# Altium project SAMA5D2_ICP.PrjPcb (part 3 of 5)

## Sheet 07 - USB HSIC to Gb Ethernet.SchDoc
size B; CompanyName: Microchip Technology Inc.; Organization: Microchip Technology; Address1: 2355 West Chandler Blvd.; Address2: Chandler, AZ  85224; Address4: USA; DocumentNumber: 8; SheetNumber: 8; SheetTotal: 15; SheetTitle: USB HSIC to Gb Ethernet
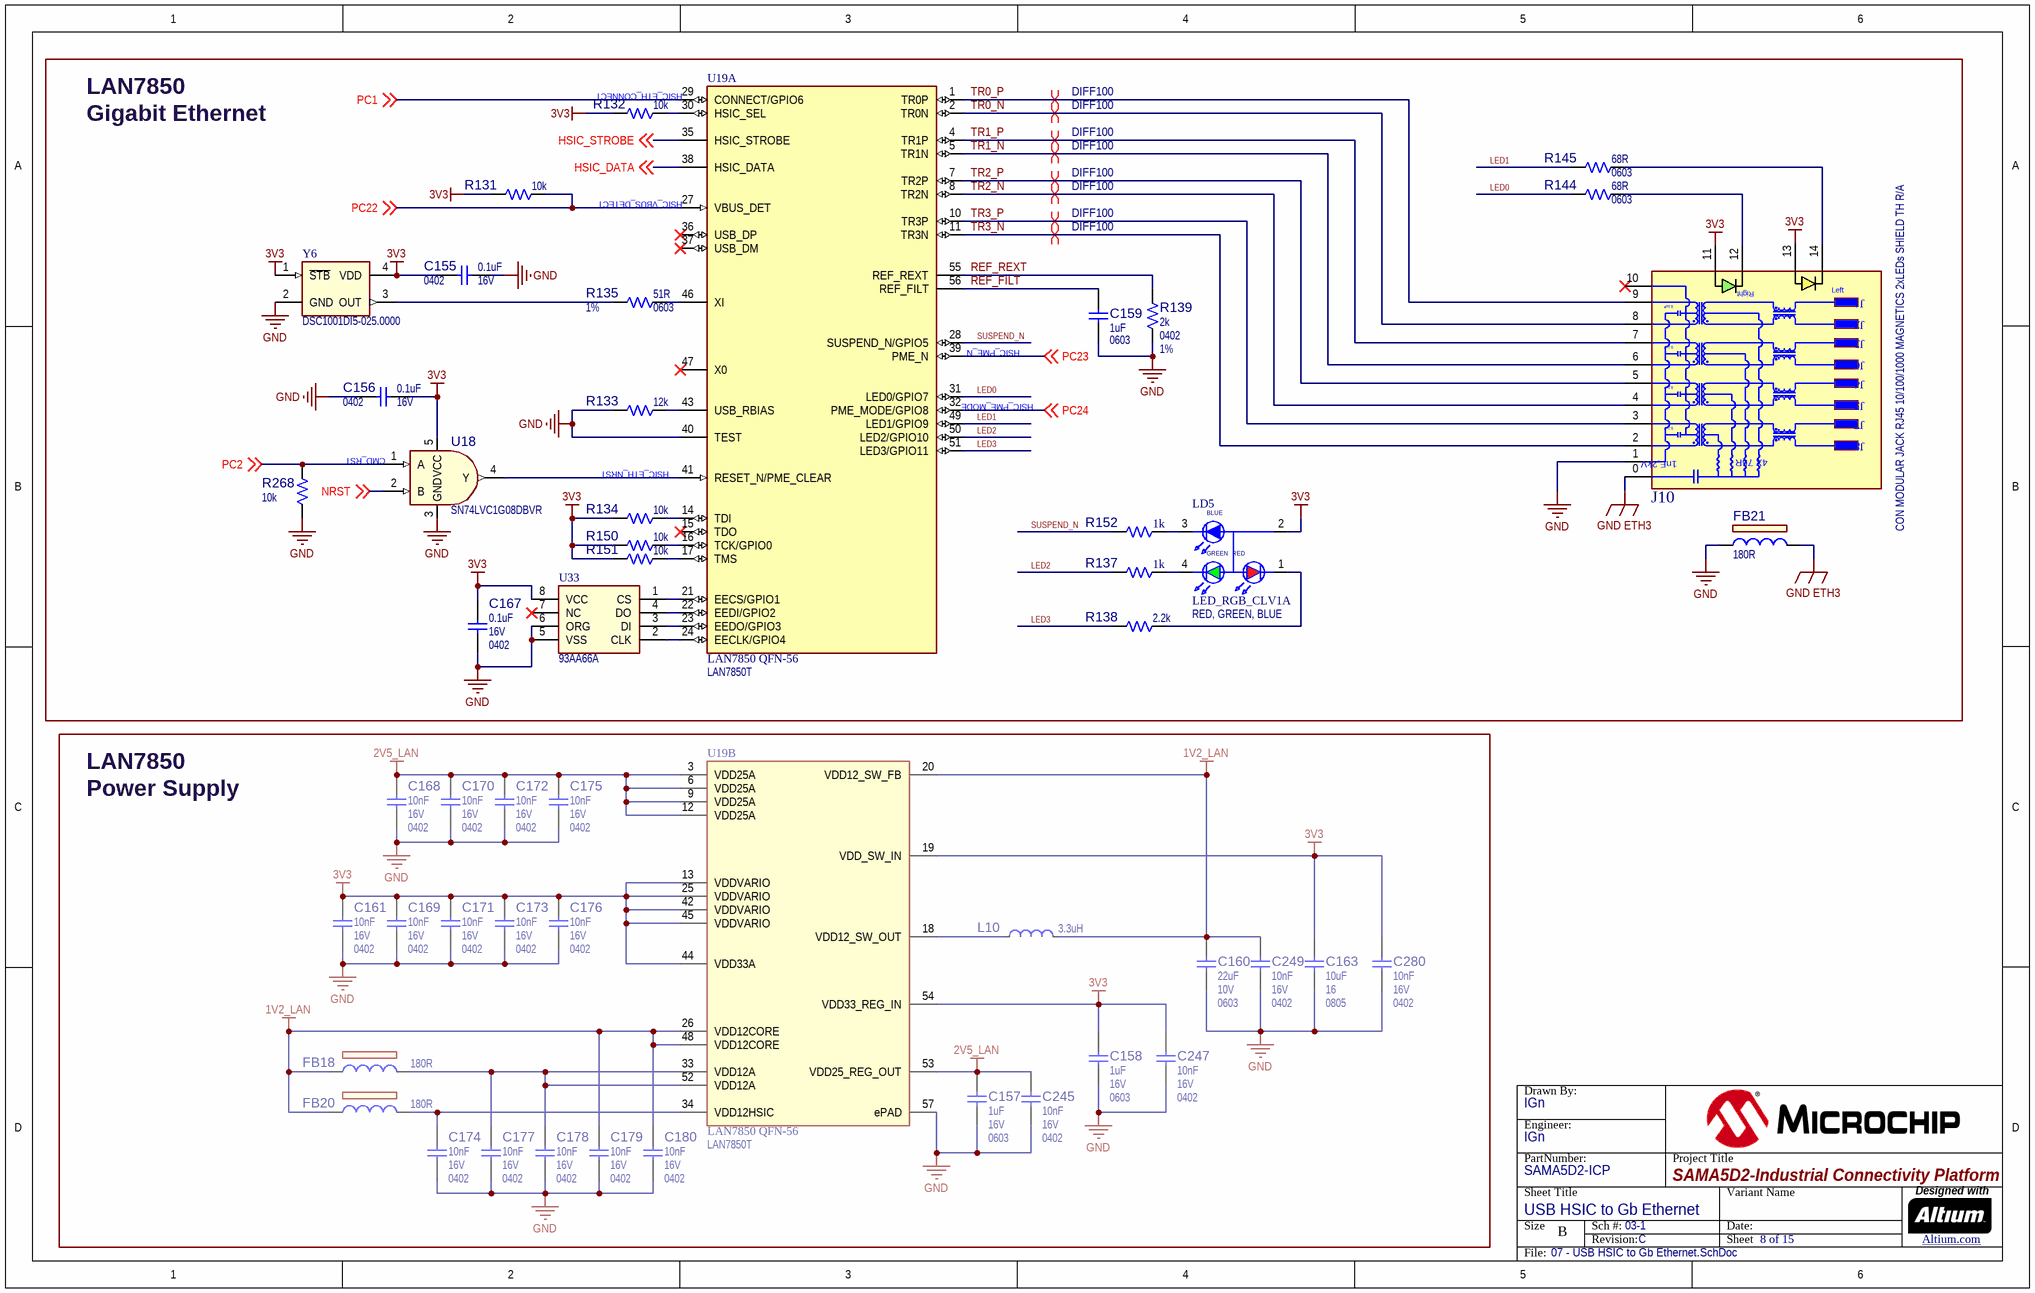
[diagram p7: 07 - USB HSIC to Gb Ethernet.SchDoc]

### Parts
(Parts that share a designator on the sheet are numbered #1, #2 ... from top to bottom, then left to right.)
?#8  (no value)  (graphical)
C155  value 0.1uF  Voltage: 16V  Package: 0402  [CAP_C_0402]  (hidden comment: Capacitor NP)
C156  value 0.1uF  Voltage: 16V  Package: 0402  [CAP_C_0402]  (hidden comment: Capacitor NP)
C157  value 1uF  Voltage: 16V  Package: 0603  [CAP_C_0603]  (hidden comment: Capacitor NP)
C158  value 1uF  Voltage: 16V  Package: 0603  [CAP_C_0603]  (hidden comment: Capacitor NP)
C159  value 1uF  Package: 0603  [CAP_C_0603]  (hidden comment: Capacitor NP)
C160  value 22uF  Voltage: 10V  Package: 0603  [CAP_C_0603]  (hidden comment: Capacitor NP)
C161  value 10nF  Voltage: 16V  Package: 0402  [CAP_C_0402]  (hidden comment: Capacitor NP)
C163  value 10uF  Voltage: 16  Package: 0805  [CAP_C_0805]  (hidden comment: Capacitor NP)
C167  value 0.1uF  Voltage: 16V  Package: 0402  [CAP_C_0402]  (hidden comment: Capacitor NP)
C168  value 10nF  Voltage: 16V  Package: 0402  [CAP_C_0402]  (hidden comment: Capacitor NP)
C169  value 10nF  Voltage: 16V  Package: 0402  [CAP_C_0402]  (hidden comment: Capacitor NP)
C170  value 10nF  Voltage: 16V  Package: 0402  [CAP_C_0402]  (hidden comment: Capacitor NP)
C171  value 10nF  Voltage: 16V  Package: 0402  [CAP_C_0402]  (hidden comment: Capacitor NP)
C172  value 10nF  Voltage: 16V  Package: 0402  [CAP_C_0402]  (hidden comment: Capacitor NP)
C173  value 10nF  Voltage: 16V  Package: 0402  [CAP_C_0402]  (hidden comment: Capacitor NP)
C174  value 10nF  Voltage: 16V  Package: 0402  [CAP_C_0402]  (hidden comment: Capacitor NP)
C175  value 10nF  Voltage: 16V  Package: 0402  [CAP_C_0402]  (hidden comment: Capacitor NP)
C176  value 10nF  Voltage: 16V  Package: 0402  [CAP_C_0402]  (hidden comment: Capacitor NP)
C177  value 10nF  Voltage: 16V  Package: 0402  [CAP_C_0402]  (hidden comment: Capacitor NP)
C178  value 10nF  Voltage: 16V  Package: 0402  [CAP_C_0402]  (hidden comment: Capacitor NP)
C179  value 10nF  Voltage: 16V  Package: 0402  [CAP_C_0402]  (hidden comment: Capacitor NP)
C180  value 10nF  Voltage: 16V  Package: 0402  [CAP_C_0402]  (hidden comment: Capacitor NP)
C245  value 10nF  Voltage: 16V  Package: 0402  [CAP_C_0402]  (hidden comment: Capacitor NP)
C247  value 10nF  Voltage: 16V  Package: 0402  [CAP_C_0402]  (hidden comment: Capacitor NP)
C249  value 10nF  Voltage: 16V  Package: 0402  [CAP_C_0402]  (hidden comment: Capacitor NP)
C280  value 10nF  Voltage: 16V  Package: 0402  [CAP_C_0402]  (hidden comment: Capacitor NP)
FB18  value 180R  [IND_C_0603]  (hidden comment: Ferrite Bead)
FB20  value 180R  [IND_C_0603]  (hidden comment: Ferrite Bead)
FB21  value 180R  [IND_C_0603]  (hidden comment: Ferrite Bead)
J10  value CON MODULAR JACK RJ45 10/100/1000 MAGNETICS 2xLEDs SHIELD TH R/A  [CON_RJ-45_TH_RA_PULSE_JD1-0001NL]  (hidden comment: CON_RJ-45_TH_RA_PULSE_JD1-0001NL)
L10  value 3.3uH  [IND_SRN3015TA]  (hidden comment: Inductor)
LD5  LED_RGB_CLV1A  value RED, GREEN, BLUE  [PLCC-4_CLV1A-FKB]
R131  value 10k  [RES_C_0402]  (hidden comment: Resistor)
R132  value 10k  [RES_C_0402]  (hidden comment: Resistor)
R133  value 12k  [RES_C_0402]  (hidden comment: Resistor)
R134  value 10k  [RES_C_0402]  (hidden comment: Resistor)
R135  value 51R  Package: 0603  Tolerance: 1%  [RES_C_0603]  (hidden comment: Resistor)
R137  value 1k  [RES_C_0603]  (hidden comment: Resistor)
R138  value 2.2k  [RES_C_0603]  (hidden comment: Resistor)
R139  value 2k  Package: 0402  Tolerance: 1%  [RES_C_0402]  (hidden comment: Resistor)
R144  value 68R  Package: 0603  [RES_C_0603]  (hidden comment: Resistor)
R145  value 68R  Package: 0603  [RES_C_0603]  (hidden comment: Resistor)
R150  value 10k  [RES_C_0402]  (hidden comment: Resistor)
R151  value 10k  [RES_C_0402]  (hidden comment: Resistor)
R152  value 1k  [RES_C_0603]  (hidden comment: Resistor)
R268  value 10k  [RES_C_0402]  (hidden comment: Resistor)
U18  value SN74LVC1G08DBVR  [SOT-23-5]  (hidden comment: 74XX1G08_9 SOT-23-5)
U19  LAN7850 QFN-56  value LAN7850T  [QFN-56_8x8_EP5.9X5.9]  (parts A,B of 2)
U33  value 93AA66A  [SOIC-8_150MIL]  (hidden comment: 93XX66A_B_C PDIP-8_SOIC-8_TSSOP-8_MSOP-8)
Y6  Manufacturer Part Number 1: DSC1001DI5-025.0000  [DFN-4_2.5x2]  (hidden comment: DSC10xx DFN-4)

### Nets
1V2_LAN: C160.2 C179.2 C180.2 C249.2 FB18.1 FB20.1 L10.2(F) U19.20(VDD12_SW_FB) U19.26(VDD12CORE) U19.48(VDD12CORE)
2V5_LAN: C157.2 C168.2 C170.2 C172.2 C175.2 C245.2 U19.3(VDD25A) U19.6(VDD25A) U19.9(VDD25A) U19.12(VDD25A) U19.53(VDD25_REG_OUT)
3V3: C155.2 C156.2 C158.2 C161.2 C163.2 C167.1 C169.2 C171.2 C173.2 C176.2 C247.2 C280.2 J10.11 J10.13 LD5.2(A) R131.2 R132.2 R134.2 R150.2 R151.2 U18.5(VCC) U19.13(VDDVARIO) U19.19(VDD_SW_IN) U19.25(VDDVARIO) U19.42(VDDVARIO) U19.44(VDD33A) U19.45(VDDVARIO) U19.54(VDD33_REG_IN) U33.8(VCC) Y6.1(~{STB}) Y6.4(VDD)
GND: C155.1 C156.1 C157.1 C158.1 C159.1 C160.1 C161.1 C163.1 C167.2 C168.1 C169.1 C170.1 C171.1 C172.1 C173.1 C174.1 C175.1 C176.1 C177.1 C178.1 C179.1 C180.1 C245.1 C247.1 C249.1 C280.1 FB21.1 J10.1 R133.2 R139.1 R268.2 U18.3(GND) U19.40(TEST) U19.57(ePAD) U33.5(VSS) U33.6(ORG) Y6.2(GND)
GND ETH3: FB21.2 J10.0
HSIC_DATA: U19.38(HSIC_DATA) ; off-sheet HSIC_DATA
HSIC_STROBE: U19.35(HSIC_STROBE) ; off-sheet HSIC_STROBE
LED0: R144.1 U19.31(LED0/GPIO7)
LED1: R145.1 U19.49(LED1/GPIO9)
LED2: R137.1 U19.50(LED2/GPIO10)
LED3: R138.1 U19.51(LED3/GPIO11)
NRST: U18.2(B) ; off-sheet NRST
PC1: U19.29(CONNECT/GPIO6) ; off-sheet PC1
PC2: R268.1 U18.1(A) ; off-sheet PC2
PC22: R131.1 U19.27(VBUS_DET) ; off-sheet PC22
PC23: U19.39(PME_N) ; off-sheet PC23
PC24: U19.32(PME_MODE/GPIO8) ; off-sheet PC24
REF_FILT: C159.2 U19.56(REF_FILT)
REF_REXT: R139.2 U19.55(REF_REXT)
SUSPEND_N: R152.1 U19.28(SUSPEND_N/GPIO5)
TR0_N: J10.8 U19.2(TR0N)
TR0_P: J10.9 U19.1(TR0P)
TR1_N: J10.6 U19.5(TR1N)
TR1_P: J10.7 U19.4(TR1P)
TR2_N: J10.4 U19.8(TR2N)
TR2_P: J10.5 U19.7(TR2P)
TR3_N: J10.2 U19.11(TR3N)
TR3_P: J10.3 U19.10(TR3P)
NetC174_2: C174.2 FB20.2 U19.34(VDD12HSIC)
NetC177_2: C177.2 C178.2 FB18.2 U19.33(VDD12A) U19.52(VDD12A)
NetJ10_12: J10.12 R144.2
NetJ10_14: J10.14 R145.2
NetL10_1: L10.1(S) U19.18(VDD12_SW_OUT)
NetLD5_1: LD5.1(Kr) R138.2
NetLD5_3: LD5.3(Kb) R152.2
NetLD5_4: LD5.4(Kg) R137.2
NetR132_1: R132.1 U19.30(HSIC_SEL)
NetR133_1: R133.1 U19.43(USB_RBIAS)
NetR134_1: R134.1 U19.14(TDI)
NetR135_1: R135.1 Y6.3(OUT)
NetR135_2: R135.2 U19.46(XI)
NetR150_1: R150.1 U19.16(TCK/GPIO0)
NetR151_1: R151.1 U19.17(TMS)
NetU18_4: U18.4(Y) U19.41(RESET_N/PME_CLEAR)
NetU19_21: U19.21(EECS/GPIO1) U33.1(CS)
NetU19_22: U19.22(EEDI/GPIO2) U33.4(DO)
NetU19_23: U19.23(EEDO/GPIO3) U33.3(DI)
NetU19_24: U19.24(EECLK/GPIO4) U33.2(CLK)

Not connected (* = marked no-connect by the designer): J10 10*; U19 15(TDO)* 36(USB_DP)* 37(USB_DM)* 47(X0)*; U33 7(NC)*

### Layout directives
differential pair; differential pair class DIFF100; net class DIFF100; rule Matched Net Lengths [Tolerance = 10mil]: TR0_N, TR0_P, TR1_N, TR1_P, TR2_N, TR2_P, TR3_N, TR3_P

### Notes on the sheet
- LAN7850
- HSIC_ETH_CONNECT
- Gigabit Ethernet
- (near U19) HSIC_VBUS_DETECT
- (near U19) HSIC_PME_N
- (near U19) HSIC_PME_MODE
- (near U18) CMD_RST
- HSIC_ETH_NRST
- Power Supply

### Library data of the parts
?#8 = Title Block B
C155 C156 C167 = CAP1033: Capacitor; Manufacturer 1: Murata; Manufacturer Part Number 1: GRM155R71C104KA88D; Description_: CAP CER 0.1uF 16V 10% X7R SMD 0402; Dev Tools Status: Production; Tolerance: 10%; Temperature Coeffcient: X7R; Type: Ceramic; Owner: Sompoch Loboonlert; Populated: Yes
C157 C158 = CAP0265: Capacitor; Manufacturer 1: AVX; Manufacturer Part Number 1: 0603YD105KAT2A; Description_: CAP CER 1uF 16V 10% X5R SMD 0603; Dev Tools Status: Production; Tolerance: 10%; Temperature Coeffcient: X5R; Type: Ceramic; Populated: Yes
C159 = CAP0265: Capacitor; Manufacturer 1: AVX; Manufacturer Part Number 1: 0603YD105KAT2A; Voltage: 16V; Description_: CAP CER 1uF 16V 10% X5R SMD 0603; Dev Tools Status: Production; Tolerance: 10%; Temperature Coeffcient: X5R; Type: Ceramic; Populated: Yes
C160 = CAP1648: Capacitor; Manufacturer 1: TDK Corporation; Manufacturer Part Number 1: C1608X5R1A226M080AC; Description_: CAP CER 22uF 10V 20% X5R SMD 0603; Dev Tools Status: Production; Tolerance: 20%; Temperature Coeffcient: X5R; Type: Ceramic; Owner: Razvan Cristescu; Populated: YES
C161 C168-C180 C245 C247 C249 C280 = CAP0611: Capacitor; Manufacturer 1: Murata; Manufacturer Part Number 1: GRM155R71C103KA01D; Description_: CAP CER 10000pF 16V 10% X7R SMD 0402; Dev Tools Status: Production; Tolerance: 10%; Temperature Coeffcient: X7R; Type: Ceramic; Populated: Yes
C163 = CAP1323: Capacitor; Manufacturer 1: Taiyo Yuden; Manufacturer Part Number 1: EMK212BB7106MG-T; Description_: CAP CER 10uF 16V 20% X7R SMD 0805; Dev Tools Status: Production; Tolerance: 20%; Temperature Coeffcient: X7R; Type: Ceramic; Owner: Rodger Griffith; Populated: YES
FB18 FB20 FB21 = IND1453: FERRITE 180R 1.5A SMD 0603; Manufacturer 1: Murata Electronics North America; Manufacturer Part Number 1: BLM18PG181SN1D; Dev Tools Status: Production; Owner: Dragos Danaila; DCR: 0.09R; Test Frequency: 100MHz; Populated: YES
J10 = CON1767: Manufacturer 1: Pulse Electronics Network; Description_: CONN MAGJACK 1PORT 1000 BASE-T; Dev Tools Status: Design; Owner: Ilie Galan; Populated: YES
L10 = IND1587: Manufacturer 1: Bourns Inc.; Manufacturer Part Number 1: SRN3015TA-3R3M; Description_: INDUCTOR 3.3uH 1.4A 20% SMD 3x3x1.5; Dev Tools Status: Design; Type: Ferrite Bead; Owner: Dragos Danaila; DCR: 0.08R; Saturation Current: 1.4A; Test Frequency: 100KHz; Populated: YES
LD5 = DIODE1214: Manufacturer 1: Cree Inc; Manufacturer Part Number 1: CLV1A-FKB-CK1N1G1BB7R4S3; Description_: DIO LED TRI RED, GREEN, BLUE 2V, 3.2V, 3.2V 20mA, 20mA, 20mA SMD 4-PLCC; Dev Tools Status: Production; Type: LED Tricolor; Forward Current: 20mA, 20mA, 20mA; Power: 130mW, 100mW, 100mW; Reverse Current: 10uA; Reverse Voltage: 5V; Owner: Randolph Sobrepena; Populated: YES
R131 R132 R134 R150 R151 = RSMT1019: Manufacturer 1: Panasonic; Manufacturer Part Number 1: ERJ-2RKF1002X; Tolerance: 1%; Description_: RES TKF 10k 1% 1/10W SMD 0402; Dev Tools Status: Production; Voltage: 50V; Temperature Coeffcient: 100ppm/C; Power: 1/10W; Owner: Brent Lanphear; Populated: Yes
R133 = RES1021: Manufacturer 1: Rohm Semiconductor; Manufacturer Part Number 1: MCR01MZPF1202; Tolerance: 1%; Description_: RES TKF 12k 1% 1/16W SMD 0402; Dev Tools Status: Production; Voltage: 50V; Temperature Coeffcient: 400ppm/C; Power: 1/16W; Owner: Tad Ahlvers; Populated: YES
R135 = RES1384: Manufacturer 1: Yageo; Manufacturer Part Number 1: RC0603FR-0751RL; Description_: RES TKF 51R 1% 1/10W SMD 0603; Dev Tools Status: Production; Voltage: 50V; Temperature Coeffcient: 100ppm/C; Circuit Type: Isolated; Power: 1/10W; Owner: Jairuz Agang-ang; Populated: YES
R137 R152 = RSMT0138: Manufacturer 1: Panasonic; Manufacturer Part Number 1: ERJ-3EKF1001V; Tolerance: 1%; Description_: RES TKF 1k 1% 1/10W SMD 0603; Dev Tools Status: Production; Voltage: 75V; Temperature Coeffcient: 100ppm/C; Power: 1/10W; Populated: Yes
R138 = RES1130: Manufacturer 1: Panasonic; Manufacturer Part Number 1: ERJ-3EKF2201V; Tolerance: 1%; Description_: RES TKF 2.2k 1% 1/10W SMD 0603; Dev Tools Status: Production; Voltage: 75V; Temperature Coeffcient: 100ppm/C; Power: 1/10W; Owner: Bogdan P (M91398); Populated: Yes
R139 = RES1437: Manufacturer 1: Panasonic Electronic Components; Manufacturer Part Number 1: ERJ-2RKF2001X; Description_: RES TKF 2k 1% 1/10W SMD 0402; Dev Tools Status: Production; Temperature Coeffcient: ±100ppm/°C; Power: 1/10W; Populated: YES
R144 R145 = RES1205: Manufacturer 1: Panasonic; Manufacturer Part Number 1: ERJ-3EKF68R0V; Tolerance: 1%; Description_: RES TKF 68R 1% 1/10W SMD 0603; Dev Tools Status: Production; Voltage: 75V; Temperature Coeffcient: 100ppm/C; Power: 1/10W; Owner: Bogdan P (M91398); Populated: Yes
R268 = RSMT1019: Manufacturer 1: Panasonic; Manufacturer Part Number 1: ERJ-2RKF1002X; Tolerance: 1%; Description_: RES TKF 10k 1% 1/10W SMD 0402; Dev Tools Status: Production; Voltage: 50V; Temperature Coeffcient: 100ppm/C; Power: 1/10W; Owner: Brent Lanphear; Populated: DNP
U18 = IC1056: Gate AND; Manufacturer 1: Texas Instruments; MCHP-ID: IC1056; Description_: IC LOGIC SN74LVC1G08DBVR Single AND Gate SOT-23-5; Dev Tools Status: Production; Owner: Stephen Humberd; Populated: YES
U19 = MIC7437: Manufacturer 1: Microchip Technology; Manufacturer Part Number 1: LAN7850T-I/8JXCT-ND; Description_: MCHP INTERFACE USB/ETHERNET/HSIC LAN7850T QFN-56; Dev Tools Status: Design; Owner: Sam Charles; Populated: YES
U33 = MIC6147: Manufacturer 1: Microchip; Manufacturer Part Number 1: 93AA66A-I/SN; Description_: MCHP MEMORY SERIAL EEPROM 4k Microwire 93AA66A-I/SN SOIC-8; MAPS Description: 4K, 512 X 8 SERIAL EE 1.8V; Dev Tools Status: Design; Owner: Tad Ahlvers; MPC: C5BJ37C2XG00; PackingMedia: TUBE; TempRange: -40C to +85C; Stage: REL; LeadCount: 8; PackageWidth: 3.90mm(.150in); ForceMinOrderQtyMult: False; MinOrderQty: 0; LeadContent: Pb-FREE; MemorySize: 4K; OpVoltMin: 1.8; OpVoltMax: 5.5; MaxClockFreq: 2 MHz; WPScheme: None; MemoryOrg: x8; Endurance: 1,000,000; Populated: YES
Y6 = MIC8282: Manufacturer 1: Microchip Technology; Description_: MCHP CLOCK OSCILLATOR SINGLE 25MHz DSC1001DI5-025.0000 DFN-4; Dev Tools Status: Design; Value: 25MHz; Owner: Ciprian Abramov; Populated: YES

## Sheet 08 - Ethernet switch.SchDoc
size B; CompanyName: Microchip Technology Inc.; Organization: Microchip Technology; Address1: 2355 West Chandler Blvd.; Address2: Chandler, AZ  85224; Address4: USA; DocumentNumber: 9; SheetNumber: 9; SheetTotal: 15; SheetTitle: Ethernet Switch
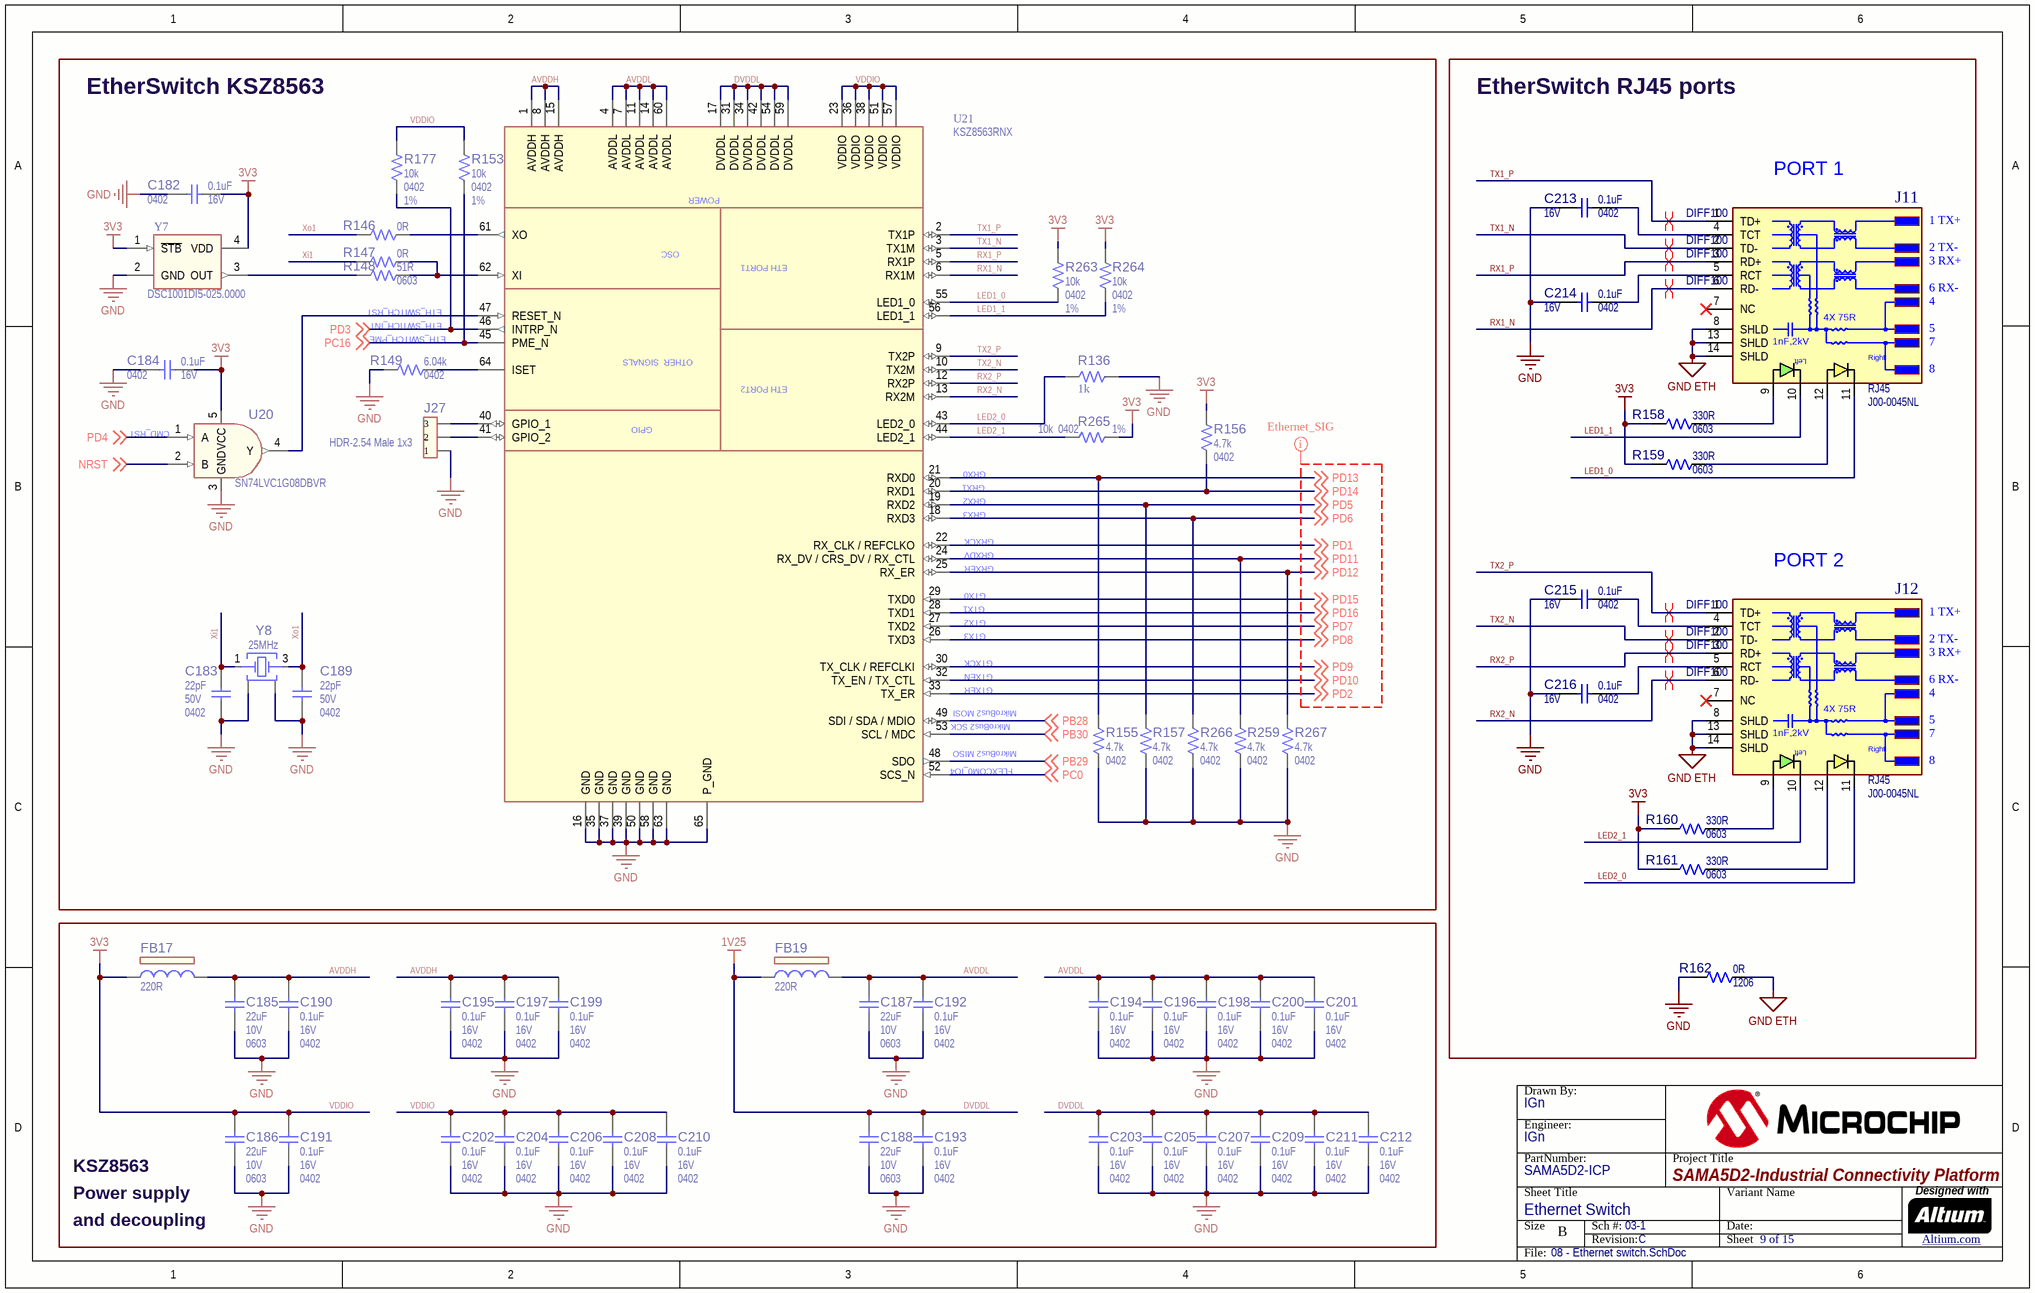
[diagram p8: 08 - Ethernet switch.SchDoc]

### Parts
(Parts that share a designator on the sheet are numbered #1, #2 ... from top to bottom, then left to right.)
?#9  (no value)  (graphical)
C182  value 0.1uF  Voltage: 16V  Package: 0402  [CAP_C_0402]  (hidden comment: Capacitor NP)
C183  value 22pF  Voltage: 50V  Package: 0402  [CAP_C_0402]  (hidden comment: Capacitor NP)
C184  value 0.1uF  Voltage: 16V  Package: 0402  [CAP_C_0402]  (hidden comment: Capacitor NP)
C185  value 22uF  Voltage: 10V  Package: 0603  [CAP_C_0603]  (hidden comment: Capacitor NP)
C186  value 22uF  Voltage: 10V  Package: 0603  [CAP_C_0603]  (hidden comment: Capacitor NP)
C187  value 22uF  Voltage: 10V  Package: 0603  [CAP_C_0603]  (hidden comment: Capacitor NP)
C188  value 22uF  Voltage: 10V  Package: 0603  [CAP_C_0603]  (hidden comment: Capacitor NP)
C189  value 22pF  Voltage: 50V  Package: 0402  [CAP_C_0402]  (hidden comment: Capacitor NP)
C190  value 0.1uF  Voltage: 16V  Package: 0402  [CAP_C_0402]  (hidden comment: Capacitor NP)
C191  value 0.1uF  Voltage: 16V  Package: 0402  [CAP_C_0402]  (hidden comment: Capacitor NP)
C192  value 0.1uF  Voltage: 16V  Package: 0402  [CAP_C_0402]  (hidden comment: Capacitor NP)
C193  value 0.1uF  Voltage: 16V  Package: 0402  [CAP_C_0402]  (hidden comment: Capacitor NP)
C194  value 0.1uF  Voltage: 16V  Package: 0402  [CAP_C_0402]  (hidden comment: Capacitor NP)
C195  value 0.1uF  Voltage: 16V  Package: 0402  [CAP_C_0402]  (hidden comment: Capacitor NP)
C196  value 0.1uF  Voltage: 16V  Package: 0402  [CAP_C_0402]  (hidden comment: Capacitor NP)
C197  value 0.1uF  Voltage: 16V  Package: 0402  [CAP_C_0402]  (hidden comment: Capacitor NP)
C198  value 0.1uF  Voltage: 16V  Package: 0402  [CAP_C_0402]  (hidden comment: Capacitor NP)
C199  value 0.1uF  Voltage: 16V  Package: 0402  [CAP_C_0402]  (hidden comment: Capacitor NP)
C200  value 0.1uF  Voltage: 16V  Package: 0402  [CAP_C_0402]  (hidden comment: Capacitor NP)
C201  value 0.1uF  Voltage: 16V  Package: 0402  [CAP_C_0402]  (hidden comment: Capacitor NP)
C202  value 0.1uF  Voltage: 16V  Package: 0402  [CAP_C_0402]  (hidden comment: Capacitor NP)
C203  value 0.1uF  Voltage: 16V  Package: 0402  [CAP_C_0402]  (hidden comment: Capacitor NP)
C204  value 0.1uF  Voltage: 16V  Package: 0402  [CAP_C_0402]  (hidden comment: Capacitor NP)
C205  value 0.1uF  Voltage: 16V  Package: 0402  [CAP_C_0402]  (hidden comment: Capacitor NP)
C206  value 0.1uF  Voltage: 16V  Package: 0402  [CAP_C_0402]  (hidden comment: Capacitor NP)
C207  value 0.1uF  Voltage: 16V  Package: 0402  [CAP_C_0402]  (hidden comment: Capacitor NP)
C208  value 0.1uF  Voltage: 16V  Package: 0402  [CAP_C_0402]  (hidden comment: Capacitor NP)
C209  value 0.1uF  Voltage: 16V  Package: 0402  [CAP_C_0402]  (hidden comment: Capacitor NP)
C210  value 0.1uF  Voltage: 16V  Package: 0402  [CAP_C_0402]  (hidden comment: Capacitor NP)
C211  value 0.1uF  Voltage: 16V  Package: 0402  [CAP_C_0402]  (hidden comment: Capacitor NP)
C212  value 0.1uF  Voltage: 16V  Package: 0402  [CAP_C_0402]  (hidden comment: Capacitor NP)
C213  value 0.1uF  Voltage: 16V  Package: 0402  [CAP_C_0402]  (hidden comment: Capacitor NP)
C214  value 0.1uF  Voltage: 16V  Package: 0402  [CAP_C_0402]  (hidden comment: Capacitor NP)
C215  value 0.1uF  Voltage: 16V  Package: 0402  [CAP_C_0402]  (hidden comment: Capacitor NP)
C216  value 0.1uF  Voltage: 16V  Package: 0402  [CAP_C_0402]  (hidden comment: Capacitor NP)
FB17  value 220R  [IND_C_0603]  (hidden comment: Ferrite Bead)
FB19  value 220R  [IND_C_0603]  (hidden comment: Ferrite Bead)
J11  value RJ45  Manufacturer Part Number 1: J00-0045NL  [J00-0045NL_RJ45_connector]  (hidden comment: RJ45 J00-0045NL)
J12  value RJ45  Manufacturer Part Number 1: J00-0045NL  [J00-0045NL_RJ45_connector]  (hidden comment: RJ45 J00-0045NL)
J27  value HDR-2.54 Male 1x3  [HDR_M_2.54_1x3]  (hidden comment: Header 1x3)
R136  value 1k  [RES_C_0603]  (hidden comment: Resistor)
R146  value 0R  [RES_C_0402]  (hidden comment: Resistor)
R147  value 0R  [RES_C_0402]  (hidden comment: Resistor)
R148  value 51R  Package: 0603  [RES_C_0603]  (hidden comment: Resistor)
R149  value 6.04k  Package: 0402  [RES_C_0402]  (hidden comment: Resistor)
R153  value 10k  Package: 0402  Tolerance: 1%  [RES_C_0402]  (hidden comment: Resistor)
R155  value 4.7k  Package: 0402  [RES_C_0402]  (hidden comment: Resistor)
R156  value 4.7k  Package: 0402  [RES_C_0402]  (hidden comment: Resistor)
R157  value 4.7k  Package: 0402  [RES_C_0402]  (hidden comment: Resistor)
R158  value 330R  Package: 0603  [RES_C_0603]  (hidden comment: Resistor)
R159  value 330R  Package: 0603  [RES_C_0603]  (hidden comment: Resistor)
R160  value 330R  Package: 0603  [RES_C_0603]  (hidden comment: Resistor)
R161  value 330R  Package: 0603  [RES_C_0603]  (hidden comment: Resistor)
R162  value 0R  Package: 1206  [RES_C_1206]  (hidden comment: Resistor)
R177  value 10k  Package: 0402  Tolerance: 1%  [RES_C_0402]  (hidden comment: Resistor)
R259  value 4.7k  Package: 0402  [RES_C_0402]  (hidden comment: Resistor)
R263  value 10k  Package: 0402  Tolerance: 1%  [RES_C_0402]  (hidden comment: Resistor)
R264  value 10k  Package: 0402  Tolerance: 1%  [RES_C_0402]  (hidden comment: Resistor)
R265  value 10k  Package: 0402  Tolerance: 1%  [RES_C_0402]  (hidden comment: Resistor)
R266  value 4.7k  Package: 0402  [RES_C_0402]  (hidden comment: Resistor)
R267  value 4.7k  Package: 0402  [RES_C_0402]  (hidden comment: Resistor)
U20  value SN74LVC1G08DBVR  [SOT-23-5]  (hidden comment: 74XX1G08_9 SOT-23-5)
U21  KSZ8563RNX  [QFN-64_8x8-EP6.5sq]
Y7  Manufacturer Part Number 1: DSC1001DI5-025.0000  [DFN-4_2.5x2]  (hidden comment: DSC10xx DFN-4)
Y8  value 25MHz  [CRYSTAL_L3.2W2.5H0.8]  (hidden comment: Crystal 4 pins 1-3)

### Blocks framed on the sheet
EtherSwitch KSZ8563: C182-C184 C189 J27 R136 R146-R149 R153 R155-R157 R177 R259 R263-R267 U20 U21 Y7 Y8
EtherSwitch RJ45 ports: C213-C216 J11 J12 R158-R162

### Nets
1V25: C188.2 C193.2 C203.2 C205.2 C207.2 C209.2 C211.2 C212.2 FB19.1 U21.17(DVDDL) U21.31(DVDDL) U21.34(DVDDL) U21.42(DVDDL) U21.54(DVDDL) U21.59(DVDDL)  [also labelled DVDDL]
3V3: C182.2 C184.2 C186.2 C191.2 C202.2 C204.2 C206.2 C208.2 C210.2 FB17.1 R153.1 R156.1 R158.1 R159.1 R160.1 R161.2 R177.2 R263.2 R264.2 R265.1 U20.5(VCC) U21.23(VDDIO) U21.36(VDDIO) U21.38(VDDIO) U21.51(VDDIO) U21.57(VDDIO) Y7.1(~{STB}) Y7.4(VDD)  [also labelled VDDIO]
GND: C182.1 C183.1 C184.1 C185.1 C186.1 C187.1 C188.1 C189.1 C190.1 C191.1 C192.1 C193.1 C194.1 C195.1 C196.1 C197.1 C198.1 C199.1 C200.1 C201.1 C202.1 C203.1 C204.1 C205.1 C206.1 C207.1 C208.1 C209.1 C210.1 C211.1 C212.1 C213.2 C214.2 C215.2 C216.2 J27.1 R136.1 R149.1 R155.2 R157.2 R162.1 R259.2 R266.2 R267.2 U20.3(GND) U21.16(GND) U21.35(GND) U21.37(GND) U21.39(GND) U21.50(GND) U21.58(GND) U21.63(GND) U21.65(P_GND) Y7.2(GND) Y8.2 Y8.4
GND ETH: J11.8(SHLD) J11.13(SHLD) J11.14(SHLD) J12.8(SHLD) J12.13(SHLD) J12.14(SHLD) R162.2
AVDDH: C185.2 C190.2 C195.2 C197.2 C199.2 FB17.2 U21.1(AVDDH) U21.8(AVDDH) U21.15(AVDDH)
AVDDL: C187.2 C192.2 C194.2 C196.2 C198.2 C200.2 C201.2 FB19.2 U21.4(AVDDL) U21.7(AVDDL) U21.11(AVDDL) U21.14(AVDDL) U21.60(AVDDL)
LED1_0: J11.11(Ag) R263.1 U21.55(LED1_0)
LED1_1: J11.10(Cy) R264.1 U21.56(LED1_1)
LED2_0: J12.11(Ag) R136.2 U21.43(LED2_0)
LED2_1: J12.10(Cy) R265.2 U21.44(LED2_1)
NRST: U20.2(B) ; off-sheet NRST
PB28: U21.49(SDI_/_SDA_/_MDIO) ; off-sheet PB28
PB29: U21.48(SDO) ; off-sheet PB29
PB30: U21.53(SCL_/_MDC) ; off-sheet PB30
PC0: U21.52(SCS_N) ; off-sheet PC0
PC16: R153.2 U21.45(PME_N) ; off-sheet PC16
PD1: U21.22(RX_CLK_/_REFCLKO) ; off-sheet PD1
PD2: U21.33(TX_ER) ; off-sheet PD2
PD3: R177.1 U21.46(INTRP_N) ; off-sheet PD3
PD4: U20.1(A) ; off-sheet PD4
PD5: R157.1 U21.19(RXD2) ; off-sheet PD5
PD6: R266.1 U21.18(RXD3) ; off-sheet PD6
PD7: U21.27(TXD2) ; off-sheet PD7
PD8: U21.26(TXD3) ; off-sheet PD8
PD9: U21.30(TX_CLK_/_REFCLKI) ; off-sheet PD9
PD10: U21.32(TX_EN_/_TX_CTL) ; off-sheet PD10
PD11: R259.1 U21.24(RX_DV_/_CRS_DV_/_RX_CTL) ; off-sheet PD11
PD12: R267.1 U21.25(RX_ER) ; off-sheet PD12
PD13: R155.1 U21.21(RXD0) ; off-sheet PD13
PD14: R156.2 U21.20(RXD1) ; off-sheet PD14
PD15: U21.29(TXD0) ; off-sheet PD15
PD16: U21.28(TXD1) ; off-sheet PD16
RX1_N: J11.6(RD-) U21.6(RX1M)
RX1_P: J11.3(RD+) U21.5(RX1P)
RX2_N: J12.6(RD-) U21.13(RX2M)
RX2_P: J12.3(RD+) U21.12(RX2P)
TX1_N: J11.2(TD-) U21.3(TX1M)
TX1_P: J11.1(TD+) U21.2(TX1P)
TX2_N: J12.2(TD-) U21.10(TX2M)
TX2_P: J12.1(TD+) U21.9(TX2P)
Xi1: C183.2 R147.1 Y8.1
Xo1: C189.2 R146.1 Y8.3
NetC213_1: C213.1 J11.4(TCT)
NetC214_1: C214.1 J11.5(RCT)
NetC215_1: C215.1 J12.4(TCT)
NetC216_1: C216.1 J12.5(RCT)
NetJ11_9: J11.9(Ay) R158.2
NetJ11_12: J11.12(Cg) R159.2
NetJ12_9: J12.9(Ay) R160.2
NetJ12_12: J12.12(Cg) R161.1
NetJ27_2: J27.2 U21.41(GPIO_2)
NetJ27_3: J27.3 U21.40(GPIO_1)
NetR146_2: R146.2 U21.61(XO)
NetR147_2: R147.2 R148.2 U21.62(XI)
NetR148_1: R148.1 Y7.3(OUT)
NetR149_2: R149.2 U21.64(ISET)
NetU20_4: U20.4(Y) U21.47(RESET_N)

Not connected (* = marked no-connect by the designer): J11 7(NC)*; J12 7(NC)*

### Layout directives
net class Ethernet_SIG; rule Matched Net Lengths [Tolerance = 10mil]: PD1, PD2, PD5, PD6, PD7, PD8, PD9, PD10, PD11, PD12, PD13, PD14, PD15, PD16
differential pair; differential pair class DIFF100; net class DIFF100; rule Matched Net Lengths [Tolerance = 10mil]: RX1_N, RX1_P, RX2_N, RX2_P, TX1_N, TX1_P, TX2_N, TX2_P

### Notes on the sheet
- (near J11) PORT 1
- ETH_SWITCH_RST
- ETH_SWTICH_INT
- (near R149) ETH_SWITCH_PME
- (near U20) CMD_RST
- (near U21) GRX1
- (near U21) GRX3
- (near U21) GRX2
- (near U21) GRX0
- (near U21) GRXER
- (near U21) GRXDV
- (near U21) GRXCK
- (near J12) PORT 2
- (near U21) GTX1
- (near U21) GTX3
- (near U21) GTX2
- (near U21) GTX0
- (near U21) GTXER
- (near U21) GTXEN
- (near U21) GTXCK
- (near U21) MikroBus2 MOSI
- (near U21) MikroBus2 SCK
- (near U21) FLEXCOM0_IO4
- (near U21) MikroBus2 MISO
- KSZ8563
- Power supply
- and decoupling

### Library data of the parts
?#9 = Title Block B
C182 C184 C190-C216 = CAP1033: as C155 on sheet 07 - USB HSIC to Gb Ethernet
C183 C189 = CAP1042: Capacitor; Manufacturer 1: Murata; Manufacturer Part Number 1: GRM1555C1H220JZ01D; Description_: CAP CER 22pF 50V 5% NP0 SMD 0402; Dev Tools Status: Production; Tolerance: 5%; Temperature Coeffcient: NP0; Type: Ceramic; Owner: Sompoch Loboonlert; Populated: DNP
C185-C188 = CAP1648: as C160 on sheet 07 - USB HSIC to Gb Ethernet
FB17 FB19 = IND1025: FERRITE 180R 1.5A SMD 0603; Manufacturer 1: Murata; Manufacturer Part Number 1: BLM18AG221SN1D; Description_: FERRITE 500mA 220R SMD 0603; Dev Tools Status: Production; Owner: Sompoch Loboonlert; RMS Current: 500ma; Test Frequency: 100 MHz; Populated: YES
J11 J12 = CON1769: Manufacturer 1: Pulse Electronics Network; Description_: CON MODULAR RJ45 ETHERNET J00-0045NL; Dev Tools Status: Production; Owner: Ilie Galan; Populated: YES
J27 = CON1105: Manufacturer 1: FCI; Manufacturer Part Number 1: 68000-103HLF; Description_: CON HDR-2.54 Male 1x3 Gold 5.84MH TH VERT; Dev Tools Status: Production; Owner: Bogdan P (M91398); Populated: DNP
R136 = RSMT0138: as R137 on sheet 07 - USB HSIC to Gb Ethernet
R146 R147 = RSMT1040: Manufacturer 1: Yageo; Manufacturer Part Number 1: RC0402JR-070RL; Description_: RES TKF 0R 1/16W SMD 0402; Dev Tools Status: Production; Power: 1/16W; Owner: Sompoch Loboonlert; Populated: DNP
R148 = RES1384: Manufacturer 1: Yageo; Manufacturer Part Number 1: RC0603FR-0751RL; Tolerance: 1%; Description_: RES TKF 51R 1% 1/10W SMD 0603; Dev Tools Status: Production; Voltage: 50V; Temperature Coeffcient: 100ppm/C; Circuit Type: Isolated; Power: 1/10W; Owner: Jairuz Agang-ang; Populated: YES
R149 = RES1495: Manufacturer 1: Rohm Semiconductor; Manufacturer Part Number 1: MCR01MRTF6041; Tolerance: 1%; Description_: RES TKF 6.04k 1% 1/16W SMD 0402; Dev Tools Status: Production; Voltage: 50V; Power: 1/16W; Owner: Mike Ragsdale; Populated: YES
R153 R177 R263-R265 = RSMT1019: Manufacturer 1: Panasonic; Manufacturer Part Number 1: ERJ-2RKF1002X; Description_: RES TKF 10k 1% 1/10W SMD 0402; Dev Tools Status: Production; Voltage: 50V; Temperature Coeffcient: 100ppm/C; Power: 1/10W; Owner: Brent Lanphear; Populated: Yes
R155-R157 R259 R266 R267 = RSMT0734: Manufacturer 1: Panasonic; Manufacturer Part Number 1: ERJ-2GEJ472X; Tolerance: 5%; Description_: RES TKF 4.7k 5% 1/10W SMD 0402; Dev Tools Status: Production; Voltage: 50V; Temperature Coeffcient: 200ppm/C; Power: 1/10W; Populated: Yes
R158-R161 = RSMT0166: Manufacturer 1: Panasonic; Manufacturer Part Number 1: ERJ-3GEYJ331V; Tolerance: 5%; Description_: RES TKF 330R 5% 1/10W SMD 0603; Dev Tools Status: Production; Voltage: 75V; Temperature Coeffcient: 200ppm/C; Power: 1/10W; Populated: Yes
R162 = RSMT0003: Manufacturer 1: Panasonic; Manufacturer Part Number 1: ERJ-8GEY0R00V; Description_: RES TKF 0R SMD 1206; Dev Tools Status: Production; Current: 2A; Populated: Yes
U20 = IC1056: as U18 on sheet 07 - USB HSIC to Gb Ethernet
U21 = MIC7332: Manufacturer 1: Microchip Technology Inc; Manufacturer Part Number 1: KSZ8563RNXI; Description_: MCHP INTERFACE ETHERNET KSZ8563RNXI QFN-64; Dev Tools Status: Production; Owner: Jennifer Hancock; Populated: YES
Y7 = MIC8282: as Y6 on sheet 07 - USB HSIC to Gb Ethernet
Y8 = OSC1159: Crystal; Manufacturer 1: ECS Inc.; Manufacturer Part Number 1: ECS-250-20-33-CKM-TR; Description_: CRYSTAL 25MHz 20pF SMD L3.2W2.5H0.8; Dev Tools Status: Design; Owner: Ciprian Abramov; Tolerance: 10ppm; Load Capacitance: 20pF; Populated: DNP

## Sheet 09 - EtherCAT interface.SchDoc
size B; CompanyName: Microchip Technology Inc.; Organization: Microchip Technology; Address1: 2355 West Chandler Blvd.; Address2: Chandler, AZ  85224; Address4: USA; DocumentNumber: 10; SheetNumber: 10; SheetTotal: 15; SheetTitle: EtherCAT interface
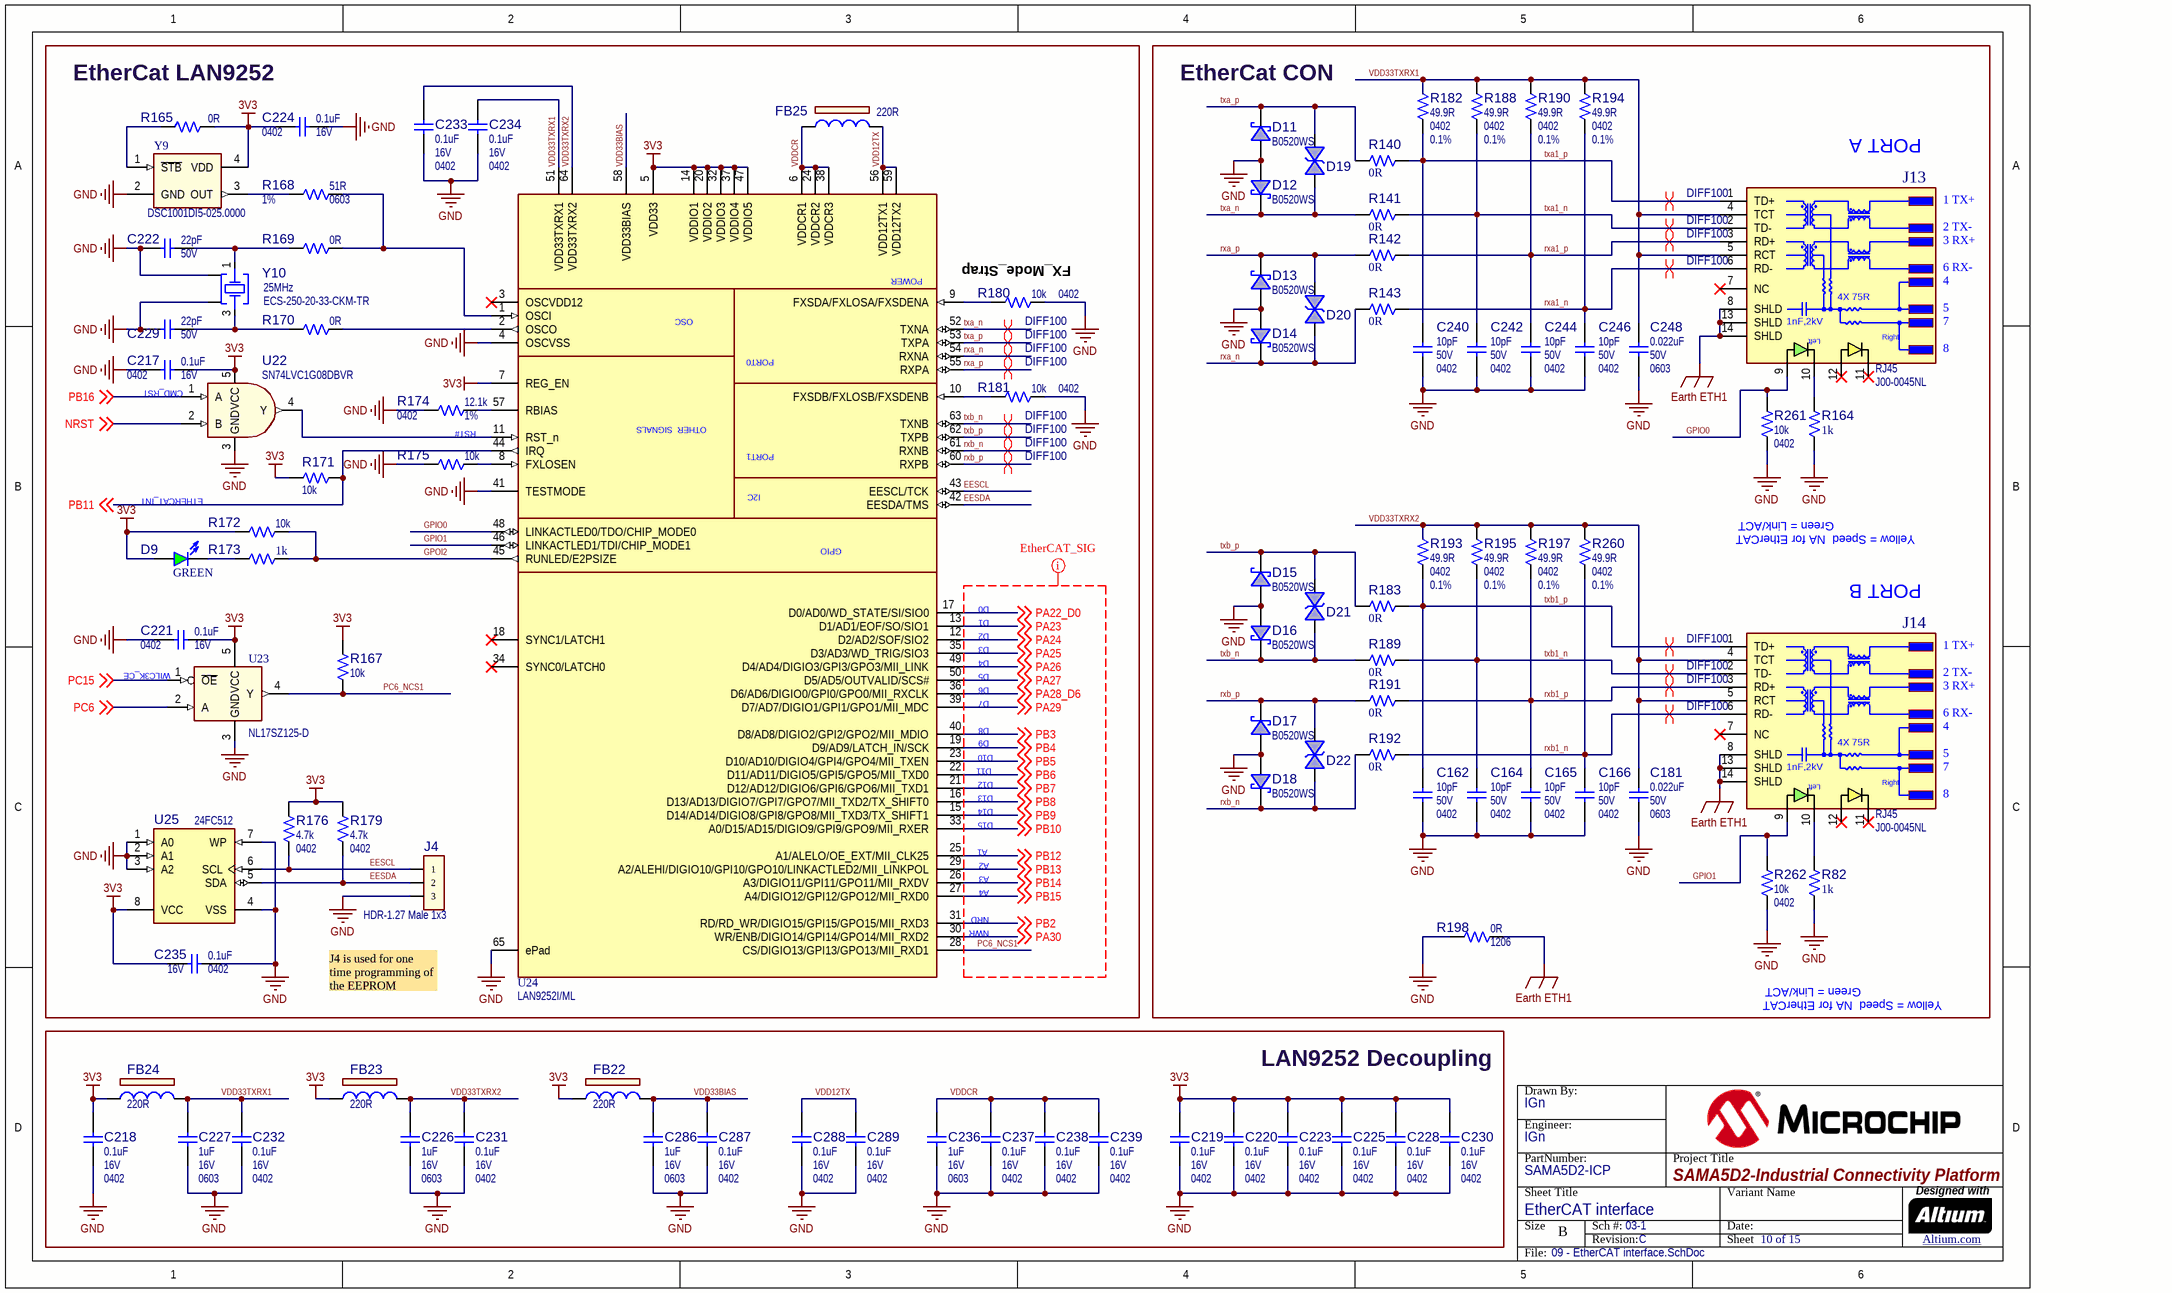
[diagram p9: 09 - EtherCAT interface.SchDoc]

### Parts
(Parts that share a designator on the sheet are numbered #1, #2 ... from top to bottom, then left to right.)
?#10  (no value)  (graphical)
C162  value 10pF  Voltage: 50V  Package: 0402  [CAP_C_0402]  (hidden comment: Capacitor NP)
C164  value 10pF  Voltage: 50V  Package: 0402  [CAP_C_0402]  (hidden comment: Capacitor NP)
C165  value 10pF  Voltage: 50V  Package: 0402  [CAP_C_0402]  (hidden comment: Capacitor NP)
C166  value 10pF  Voltage: 50V  Package: 0402  [CAP_C_0402]  (hidden comment: Capacitor NP)
C181  value 0.022uF  Voltage: 50V  Package: 0603  [CAP_C_0603]  (hidden comment: Capacitor NP)
C217  value 0.1uF  Voltage: 16V  Package: 0402  [CAP_C_0402]  (hidden comment: Capacitor NP)
C218  value 0.1uF  Voltage: 16V  Package: 0402  [CAP_C_0402]  (hidden comment: Capacitor NP)
C219  value 0.1uF  Voltage: 16V  Package: 0402  [CAP_C_0402]  (hidden comment: Capacitor NP)
C220  value 0.1uF  Voltage: 16V  Package: 0402  [CAP_C_0402]  (hidden comment: Capacitor NP)
C221  value 0.1uF  Voltage: 16V  Package: 0402  [CAP_C_0402]  (hidden comment: Capacitor NP)
C222  value 22pF  Voltage: 50V  [CAP_C_0402]  (hidden comment: Capacitor NP)
C223  value 0.1uF  Voltage: 16V  Package: 0402  [CAP_C_0402]  (hidden comment: Capacitor NP)
C224  value 0.1uF  Voltage: 16V  Package: 0402  [CAP_C_0402]  (hidden comment: Capacitor NP)
C225  value 0.1uF  Voltage: 16V  Package: 0402  [CAP_C_0402]  (hidden comment: Capacitor NP)
C226  value 1uF  Voltage: 16V  Package: 0603  [CAP_C_0603]  (hidden comment: Capacitor NP)
C227  value 1uF  Voltage: 16V  Package: 0603  [CAP_C_0603]  (hidden comment: Capacitor NP)
C228  value 0.1uF  Voltage: 16V  Package: 0402  [CAP_C_0402]  (hidden comment: Capacitor NP)
C229  value 22pF  Voltage: 50V  [CAP_C_0402]  (hidden comment: Capacitor NP)
C230  value 0.1uF  Voltage: 16V  Package: 0402  [CAP_C_0402]  (hidden comment: Capacitor NP)
C231  value 0.1uF  Voltage: 16V  Package: 0402  [CAP_C_0402]  (hidden comment: Capacitor NP)
C232  value 0.1uF  Voltage: 16V  Package: 0402  [CAP_C_0402]  (hidden comment: Capacitor NP)
C233  value 0.1uF  Voltage: 16V  Package: 0402  [CAP_C_0402]  (hidden comment: Capacitor NP)
C234  value 0.1uF  Voltage: 16V  Package: 0402  [CAP_C_0402]  (hidden comment: Capacitor NP)
C235  value 0.1uF  Voltage: 16V  Package: 0402  [CAP_C_0402]  (hidden comment: Capacitor NP)
C236  value 1uF  Voltage: 16V  Package: 0603  [CAP_C_0603]  (hidden comment: Capacitor NP)
C237  value 0.1uF  Voltage: 16V  Package: 0402  [CAP_C_0402]  (hidden comment: Capacitor NP)
C238  value 0.1uF  Voltage: 16V  Package: 0402  [CAP_C_0402]  (hidden comment: Capacitor NP)
C239  value 0.1uF  Voltage: 16V  Package: 0402  [CAP_C_0402]  (hidden comment: Capacitor NP)
C240  value 10pF  Voltage: 50V  Package: 0402  [CAP_C_0402]  (hidden comment: Capacitor NP)
C242  value 10pF  Voltage: 50V  Package: 0402  [CAP_C_0402]  (hidden comment: Capacitor NP)
C244  value 10pF  Voltage: 50V  Package: 0402  [CAP_C_0402]  (hidden comment: Capacitor NP)
C246  value 10pF  Voltage: 50V  Package: 0402  [CAP_C_0402]  (hidden comment: Capacitor NP)
C248  value 0.022uF  Voltage: 50V  Package: 0603  [CAP_C_0603]  (hidden comment: Capacitor NP)
C286  value 1uF  Voltage: 16V  Package: 0603  [CAP_C_0603]  (hidden comment: Capacitor NP)
C287  value 0.1uF  Voltage: 16V  Package: 0402  [CAP_C_0402]  (hidden comment: Capacitor NP)
C288  value 0.1uF  Voltage: 16V  Package: 0402  [CAP_C_0402]  (hidden comment: Capacitor NP)
C289  value 0.1uF  Voltage: 16V  Package: 0402  [CAP_C_0402]  (hidden comment: Capacitor NP)
D9  value GREEN  [LED_0603_GREEN]  (hidden comment: LED_green)
D11  value B0520WS  [SOD-323]  (hidden comment: Diode Schottky)
D12  value B0520WS  [SOD-323]  (hidden comment: Diode Schottky)
D13  value B0520WS  [SOD-323]  (hidden comment: Diode Schottky)
D14  value B0520WS  [SOD-323]  (hidden comment: Diode Schottky)
D15  value B0520WS  [SOD-323]  (hidden comment: Diode Schottky)
D16  value B0520WS  [SOD-323]  (hidden comment: Diode Schottky)
D17  value B0520WS  [SOD-323]  (hidden comment: Diode Schottky)
D18  value B0520WS  [SOD-323]  (hidden comment: Diode Schottky)
D19  Diode TVS Bidirectional  [DIO_C_0402]  (value not drawn)
D20  Diode TVS Bidirectional  [DIO_C_0402]  (value not drawn)
D21  Diode TVS Bidirectional  [DIO_C_0402]  (value not drawn)
D22  Diode TVS Bidirectional  [DIO_C_0402]  (value not drawn)
FB22  value 220R  [IND_C_0603]  (hidden comment: Ferrite Bead)
FB23  value 220R  [IND_C_0603]  (hidden comment: Ferrite Bead)
FB24  value 220R  [IND_C_0603]  (hidden comment: Ferrite Bead)
FB25  value 220R  [IND_C_0603]  (hidden comment: Ferrite Bead)
J4  value HDR-1.27 Male 1x3  [HDR_M_1.27_1x3]  (hidden comment: Header 1x3)
J13  value RJ45  Manufacturer Part Number 1: J00-0045NL  [J00-0045NL_RJ45_connector]  (hidden comment: RJ45 J00-0045NL)
J14  value RJ45  Manufacturer Part Number 1: J00-0045NL  [J00-0045NL_RJ45_connector]  (hidden comment: RJ45 J00-0045NL)
R82  value 1k  [RES_C_0603]  (hidden comment: Resistor)
R140  value 0R  [RES_C_0603]  (hidden comment: Resistor)
R141  value 0R  [RES_C_0603]  (hidden comment: Resistor)
R142  value 0R  [RES_C_0603]  (hidden comment: Resistor)
R143  value 0R  [RES_C_0603]  (hidden comment: Resistor)
R164  value 1k  [RES_C_0603]  (hidden comment: Resistor)
R165  value 0R  [RES_C_0402]  (hidden comment: Resistor)
R167  value 10k  [RES_C_0402]  (hidden comment: Resistor)
R168  value 51R  Package: 0603  Tolerance: 1%  [RES_C_0603]  (hidden comment: Resistor)
R169  value 0R  [RES_C_0402]  (hidden comment: Resistor)
R170  value 0R  [RES_C_0402]  (hidden comment: Resistor)
R171  value 10k  [RES_C_0402]  (hidden comment: Resistor)
R172  value 10k  [RES_C_0402]  (hidden comment: Resistor)
R173  value 1k  [RES_C_0603]  (hidden comment: Resistor)
R174  value 12.1k  Package: 0402  Tolerance: 1%  [RES_C_0402]  (hidden comment: Resistor)
R175  value 10k  [RES_C_0402]  (hidden comment: Resistor)
R176  value 4.7k  Package: 0402  [RES_C_0402]  (hidden comment: Resistor)
R179  value 4.7k  Package: 0402  [RES_C_0402]  (hidden comment: Resistor)
R180  value 10k  Package: 0402  [RES_C_0402]  (hidden comment: Resistor)
R181  value 10k  Package: 0402  [RES_C_0402]  (hidden comment: Resistor)
R182  value 49.9R  Package: 0402  Tolerance: 0.1%  [RES_C_0402]  (hidden comment: Resistor)
R183  value 0R  [RES_C_0603]  (hidden comment: Resistor)
R188  value 49.9R  Package: 0402  Tolerance: 0.1%  [RES_C_0402]  (hidden comment: Resistor)
R189  value 0R  [RES_C_0603]  (hidden comment: Resistor)
R190  value 49.9R  Package: 0402  Tolerance: 0.1%  [RES_C_0402]  (hidden comment: Resistor)
R191  value 0R  [RES_C_0603]  (hidden comment: Resistor)
R192  value 0R  [RES_C_0603]  (hidden comment: Resistor)
R193  value 49.9R  Package: 0402  Tolerance: 0.1%  [RES_C_0402]  (hidden comment: Resistor)
R194  value 49.9R  Package: 0402  Tolerance: 0.1%  [RES_C_0402]  (hidden comment: Resistor)
R195  value 49.9R  Package: 0402  Tolerance: 0.1%  [RES_C_0402]  (hidden comment: Resistor)
R197  value 49.9R  Package: 0402  Tolerance: 0.1%  [RES_C_0402]  (hidden comment: Resistor)
R198  value 0R  Package: 1206  [RES_C_1206]  (hidden comment: Resistor)
R260  value 49.9R  Package: 0402  Tolerance: 0.1%  [RES_C_0402]  (hidden comment: Resistor)
R261  value 10k  Package: 0402  [RES_C_0402]  (hidden comment: Resistor)
R262  value 10k  Package: 0402  [RES_C_0402]  (hidden comment: Resistor)
U22  value SN74LVC1G08DBVR  [SOT-23-5]  (hidden comment: 74XX1G08_9 SOT-23-5)
U23  value NL17SZ125-D  [SOT-353]  (hidden comment: NL17SZ125-D SOT-353)
U24  value LAN9252I/ML  [QFN-64_9X9_EP6]  (hidden comment: LAN9252 QFN-64)
U25  value 24FC512  [SOIC-8]  (hidden comment: 24XX01_02_04_08_16_32_64_128_256_512_1025 SOIC-8_SOIJ-8_TSSOP-8_PDIP-8_MSOP-8)
Y9  Manufacturer Part Number 1: DSC1001DI5-025.0000  [DFN-4_2.5x2]  (hidden comment: DSC10xx DFN-4)
Y10  value 25MHz  Manufacturer Part Number 1: ECS-250-20-33-CKM-TR  [CRYSTAL_L3.2W2.5H0.8]  (hidden comment: Crystal 4 pins 1-3)

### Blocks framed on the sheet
EtherCat LAN9252: C217 C221 C222 C224 C229 C233-C235 D9 FB25 J4 R165 R167-R176 R179-R181 U22-U25 Y9 Y10
EtherCat CON: C162 C164-C166 C181 C240 C242 C244 C246 C248 D11-D22 J13 J14 R82 R140-R143 R164 R182 R183 R188-R195 R197 R198 R260-R262
LAN9252 Decoupling: C218-C220 C223 C225-C228 C230-C232 C236-C239 C286-C289 FB22-FB24

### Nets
3V3: C217.2 C218.2 C219.2 C220.2 C221.2 C223.2 C224.2 C225.2 C228.2 C230.2 C235.2 D9.1(A) FB22.1 FB23.1 FB24.1 R165.2 R167.2 R171.2 R172.1 R176.2 R179.2 U22.5(VCC) U23.5(VCC) U24.5(VDD33) U24.7(REG_EN) U24.14(VDDIO1) U24.20(VDDIO2) U24.32(VDDIO3) U24.37(VDDIO4) U24.47(VDDIO5) U25.8(VCC) Y9.4(VDD)
Earth ETH1: J13.8(SHLD) J13.13(SHLD) J13.14(SHLD) J14.8(SHLD) J14.13(SHLD) J14.14(SHLD) R198.2
GND: C162.1 C164.1 C165.1 C166.1 C181.1 C217.1 C218.1 C219.1 C220.1 C221.1 C222.1 C223.1 C224.1 C225.1 C226.1 C227.1 C228.1 C229.1 C230.1 C231.1 C232.1 C233.1 C234.1 C235.1 C236.1 C237.1 C238.1 C239.1 C240.1 C242.1 C244.1 C246.1 C248.1 C286.1 C287.1 C288.1 C289.1 D11.1(A) D12.1(A) D13.1(A) D14.1(A) D15.1(A) D16.1(A) D17.1(A) D18.1(A) J4.3 R82.1 R164.1 R174.2 R175.1 R180.2 R181.2 R198.1 R261.1 R262.1 U22.3(GND) U23.3(GND) U24.4(OSCVSS) U24.41(TESTMODE) U24.65(ePad) U25.1(A0) U25.2(A1) U25.3(A2) U25.4(VSS) U25.7(WP) Y9.2(GND) Y10.2 Y10.4
EESCL: J4.1 R176.1 U24.43(EESCL/TCK) U25.6(SCL)
EESDA: J4.2 R179.1 U24.42(EESDA/TMS) U25.5(SDA)
GPIO0: J13.9(Ay) R261.2 U24.48(LINKACTLED0/TDO/CHIP_MODE0)
GPIO1: J14.9(Ay) R262.2 U24.46(LINKACTLED1/TDI/CHIP_MODE1)
GPOI2: R172.2 R173.2 U24.45(RUNLED/E2PSIZE)
NRST: U22.2(B) ; off-sheet NRST
PA22_D0: U24.17(D0/AD0/WD_STATE/SI/SIO0) ; off-sheet PA22_D0
PA23: U24.13(D1/AD1/EOF/SO/SIO1) ; off-sheet PA23
PA24: U24.12(D2/AD2/SOF/SIO2) ; off-sheet PA24
PA25: U24.35(D3/AD3/WD_TRIG/SIO3) ; off-sheet PA25
PA26: U24.49(D4/AD4/DIGIO3/GPI3/GPO3/MII_LINK) ; off-sheet PA26
PA27: U24.50(D5/AD5/OUTVALID/SCS#) ; off-sheet PA27
PA28_D6: U24.36(D6/AD6/DIGIO0/GPI0/GPO0/MII_RXCLK) ; off-sheet PA28_D6
PA29: U24.39(D7/AD7/DIGIO1/GPI1/GPO1/MII_MDC) ; off-sheet PA29
PA30: U24.30(WR/ENB/DIGIO14/GPI14/GPO14/MII_RXD2) ; off-sheet PA30
PB2: U24.31(RD/RD_WR/DIGIO15/GPI15/GPO15/MII_RXD3) ; off-sheet PB2
PB3: U24.40(D8/AD8/DIGIO2/GPI2/GPO2/MII_MDIO) ; off-sheet PB3
PB4: U24.19(D9/AD9/LATCH_IN/SCK) ; off-sheet PB4
PB5: U24.23(D10/AD10/DIGIO4/GPI4/GPO4/MII_TXEN) ; off-sheet PB5
PB6: U24.22(D11/AD11/DIGIO5/GPI5/GPO5/MII_TXD0) ; off-sheet PB6
PB7: U24.21(D12/AD12/DIGIO6/GPI6/GPO6/MII_TXD1) ; off-sheet PB7
PB8: U24.16(D13/AD13/DIGIO7/GPI7/GPO7/MII_TXD2/TX_SHIFT0) ; off-sheet PB8
PB9: U24.15(D14/AD14/DIGIO8/GPI8/GPO8/MII_TXD3/TX_SHIFT1) ; off-sheet PB9
PB10: U24.33(A0/D15/AD15/DIGIO9/GPI9/GPO9/MII_RXER) ; off-sheet PB10
PB11: R171.1 U24.44(IRQ) ; off-sheet PB11
PB12: U24.25(A1/ALELO/OE_EXT/MII_CLK25) ; off-sheet PB12
PB13: U24.29(A2/ALEHI/DIGIO10/GPI10/GPO10/LINKACTLED2/MII_LINKPOL) ; off-sheet PB13
PB14: U24.26(A3/DIGIO11/GPI11/GPO11/MII_RXDV) ; off-sheet PB14
PB15: U24.27(A4/DIGIO12/GPI12/GPO12/MII_RXD0) ; off-sheet PB15
PB16: U22.1(A) ; off-sheet PB16
PC6: U23.2(A) ; off-sheet PC6
PC6_NCS1: R167.1 U23.4(Y) U24.28(CS/DIGIO13/GPI13/GPO13/MII_RXD1)
PC15: U23.1(~{OE}) ; off-sheet PC15
rxa1_n: C246.2 J13.6(RD-) R143.1 R194.1
rxa1_p: C244.2 J13.3(RD+) R142.1 R190.1
rxa_n: D14.2(K) D20.1(A) R143.2 U24.54(RXNA)
rxa_p: D13.2(K) D20.2(K) R142.2 U24.55(RXPA)
rxb1_n: C166.2 J14.6(RD-) R192.1 R260.1
rxb1_p: C165.2 J14.3(RD+) R191.1 R197.1
rxb_n: D18.2(K) D22.2(K) R192.2 U24.61(RXNB)
rxb_p: D17.2(K) D22.1(A) R191.2 U24.60(RXPB)
txa1_n: C242.2 J13.2(TD-) R141.1 R188.1
txa1_p: C240.2 J13.1(TD+) R140.1 R182.1
txa_n: D12.2(K) D19.2(K) R141.2 U24.52(TXNA)
txa_p: D11.2(K) D19.1(A) R140.2 U24.53(TXPA)
txb1_n: C164.2 J14.2(TD-) R189.1 R195.1
txb1_p: C162.2 J14.1(TD+) R183.1 R193.1
txb_n: D16.2(K) D21.2(K) R189.2 U24.63(TXNB)
txb_p: D15.2(K) D21.1(A) R183.2 U24.62(TXPB)
VDD12TX: C288.2 C289.2 FB25.2 U24.56(VDD12TX1) U24.59(VDD12TX2)
VDD33BIAS: C286.2 C287.2 FB22.2 U24.58(VDD33BIAS)
VDD33TXRX1: C227.2 C232.2 C234.2 C248.2 FB24.2 J13.4(TCT) J13.5(RCT) R182.2 R188.2 R190.2 R194.2 U24.51(VDD33TXRX1)
VDD33TXRX2: C181.2 C226.2 C231.2 C233.2 FB23.2 J14.4(TCT) J14.5(RCT) R193.2 R195.2 R197.2 R260.2 U24.64(VDD33TXRX2)
VDDCR: C236.2 C237.2 C238.2 C239.2 FB25.1 U24.6(VDDCR1) U24.24(VDDCR2) U24.38(VDDCR3)
NetC222_2: C222.2 R169.1 Y10.1
NetC229_2: C229.2 R170.1 Y10.3
NetD9_2: D9.2(K) R173.1
NetJ13_10: J13.10(Cy) R164.2
NetJ14_10: J14.10(Cy) R82.2
NetR165_1: R165.1 Y9.1(~{STB})
NetR168_1: R168.1 Y9.3(OUT)
NetR168_2: R168.2 R169.2 U24.1(OSCI)
NetR170_2: R170.2 U24.2(OSCO)
NetR174_1: R174.1 U24.57(RBIAS)
NetR175_2: R175.2 U24.8(FXLOSEN)
NetR180_1: R180.1 U24.9(FXSDA/FXLOSA/FXSDENA)
NetR181_1: R181.1 U24.10(FXSDB/FXLOSB/FXSDENB)
NetU22_4: U22.4(Y) U24.11(RST_n)

Not connected (* = marked no-connect by the designer): J13 7(NC)* 11(Ag)* 12(Cg)*; J14 7(NC)* 11(Ag)* 12(Cg)*; U24 3(OSCVDD12)* 18(SYNC1/LATCH1)* 34(SYNC0/LATCH0)*

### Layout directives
differential pair; differential pair class DIFF100; net class DIFF100; rule Matched Net Lengths [Tolerance = 10mil]: rxa1_n, rxa1_p, rxa_n, rxa_p, rxb1_n, rxb1_p, rxb_n, rxb_p, txa1_n, txa1_p, txa_n, txa_p, txb1_n, txb1_p, txb_n, txb_p
net class EtherCAT_SIG: PA22_D0, PA23, PA24, PA25, PA26, PA27, PA28_D6, PA29, PA30, PB2, PB3, PB4, PB5, PB6, PB7, PB8, PB9, PB10, PB12, PB13, PB14, PB15, PC6_NCS1

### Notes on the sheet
- (near J13) PORT A
- FX_Mode_Strap
- CMD_RST
- RST#
- ETHERCAT_INT
- Green = Link/ACT
- Yellow = Speed  NA for EtherCAT
- (near U24) D0
- (near U24) D1
- (near U24) D2
- (near U24) D3
- (near J14) PORT B
- WILC3K_CE
- (near U24) D4
- (near U24) D5
- (near U24) D6
- (near U24) D7
- (near U24) D8
- (near U24) D9
- (near U24) D11
- (near U24) D10
- (near U24) D12
- (near U24) A1
- (near U24) D13
- (near U24) D14
- (near U24) D15
- (near U24) A2
- (near U24) A3
- (near U24) A4
- (near U24) NRD
- (near U24) NWR
- J4 is used for one time programming of the EEPROM

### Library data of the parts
?#10 = Title Block B
C162 C164-C166 C240 C242 C244 C246 = CAP0613: Capacitor; Manufacturer 1: Murata; Manufacturer Part Number 1: GRM1555C1H100JZ01D; Description_: CAP CER 10pF 50V 5% NP0 SMD 0402; Dev Tools Status: Production; Tolerance: 5%; Temperature Coeffcient: NP0; Type: Ceramic; Populated: YES
C181 C248 = CAP1058: Capacitor; Manufacturer 1: TDK; Manufacturer Part Number 1: C1608X7R1H223K; Description_: CAP CER 0.022uF 50V 10% X7R SMD 0603; Dev Tools Status: Production; Tolerance: 10%; Temperature Coeffcient: X7R; Type: Ceramic; Owner: Petnarong Chaijaroong; Populated: YES
C217-C221 C223-C225 C228 C230-C235 C237-C239 C287-C289 = CAP1033: as C155 on sheet 07 - USB HSIC to Gb Ethernet
C222 C229 = CAP1042: as C183 on sheet 08 - Ethernet switch
C226 C227 C236 C286 = CAP0265: as C157 on sheet 07 - USB HSIC to Gb Ethernet
D9 = DIODE1309: LED; Manufacturer 1: Wurth Electronics Inc; Manufacturer Part Number 1: 150060GS75000; Description_: DIO LED GREEN 3.2V 20mA 430mcd Clear SMD 0603; Dev Tools Status: Production; Type: LED Single; Forward Current: 20mA; Owner: Tad Ahlvers; Populated: YES
D11-D18 = DIODE1008: DIO SCTKY RB160M-60TR 550mV 1A 60V SMD SOD-123F; Manufacturer 1: Diodes Incorporated; Manufacturer Part Number 1: B0520WS-7-F; Description_: DIO SCTKY B0520WS 430mV 500mA 20V SOD-323; Dev Tools Status: Production; Type: Schottky Single; Forward Current: 500mA; Power: 235mW; Reverse Current: 250uA; Reverse Voltage: 20V; Owner: Sompoch Loboonlert; Populated: Yes
D19-D22 = DIODE1322: Manufacturer 1: AVX Corporation; Value: GG040205170N2P; Description_: DIO TVS GG040205170N2P 5V 80W SMD  0402; Dev Tools Status: Design; Power: 80W; Reverse Voltage: 5V; Owner: Sam Charles; Populated: YES
FB22-FB25 = IND1025: as FB17 on sheet 08 - Ethernet switch
J4 = CON1345: Manufacturer 1: Samtec; Manufacturer Part Number 1: TMS-103-01-G-S; Description_: CON HDR-1.27 Male 1x3 Gold TH; Dev Tools Status: Production; Owner: Jamus Griego; Populated: DNP
J13 J14 = CON1769: as J11 on sheet 08 - Ethernet switch
R82 R164 R173 = RSMT0138: as R137 on sheet 07 - USB HSIC to Gb Ethernet
R140-R143 R183 R189 R191 R192 = RSMT0001: Manufacturer 1: Panasonic; Manufacturer Part Number 1: ERJ-3GSY0R00V; Description_: RES TKF 0R 1/10W SMD 0603; Dev Tools Status: Production; Power: 1/10W; Populated: Yes
R165 = RSMT1040: Manufacturer 1: Yageo; Manufacturer Part Number 1: RC0402JR-070RL; Description_: RES TKF 0R 1/16W SMD 0402; Dev Tools Status: Production; Power: 1/16W; Owner: Sompoch Loboonlert; Populated: YES
R167 R171 R172 R175 R180 R181 R261 R262 = RSMT1019: as R131 on sheet 07 - USB HSIC to Gb Ethernet
R168 = RES1384: as R135 on sheet 07 - USB HSIC to Gb Ethernet
R169 R170 = RSMT1040: as R146 on sheet 08 - Ethernet switch
R174 = RES1490: Manufacturer 1: Rohm Semiconductor; Manufacturer Part Number 1: MCR01MRTF1212; Description_: RES TKF 12.1k 1% 1/16W SMD 0402; Dev Tools Status: Design; Voltage: 50V; Power: 1/16W; Owner: Mike Ragsdale; Populated: YES
R176 R179 = RSMT0734: as R155 on sheet 08 - Ethernet switch
R182 R188 R190 R193-R195 R197 R260 = RES1498: Manufacturer 1: Panasonic Electronic Components; Manufacturer Part Number 1: ERA-2AEB49R9X; Description_: RES TF 49.9R 0.1% 1/16W SMD 0402; Dev Tools Status: Design; Temperature Coeffcient: 25ppm/C; Power: 1/16W; Owner: Jose Garcia; Populated: YES
R198 = RSMT0003: as R162 on sheet 08 - Ethernet switch
U22 = IC1056: as U18 on sheet 07 - USB HSIC to Gb Ethernet
U23 = IC1433: Manufacturer 1: ON Semiconductor; Manufacturer Part Number 1: NL17SZ125DFT2G; MCHP-ID: IC1433; Description_: IC BUFFER NL17SZ125DFT2G TRI-ST NON-INV SOT-353; Dev Tools Status: Design; Vin: −0.5V to +7.0V; Owner: Alexandru Chiser - M19201; Populated: YES
U24 = MIC7449: Manufacturer 1: Microchip Technology; Description_: MCHP INTERFACE ETHERNET LAN9252I/ML 64QFN; Dev Tools Status: Design; Owner: Dragos Danaila; Populated: YES
U25 = MIC7059: EEPROM I2C; Manufacturer 1: Microchip Technology; Manufacturer Part Number 1: 24FC512T-I/SN; Description_: MCHP MEMORY SERIAL EEPROM 512kb 1MHZ I2C 24FC512T-I/SN SOIC-8; MAPS Description: 512K, 64K X 8, 1MHz SER EE, IND; Dev Tools Status: Design; Owner: Sam Charles; MPC: DEDX2TC2XC00; PackingMedia: T/R; TempRange: -40C to +85C; Stage: REL; LeadCount: 8; PackageWidth: 3.90mm(.150in); ForceMinOrderQtyMult: True; MinOrderQty: 3300; LeadContent: Pb-FREE; MemorySize: 512K; OpVoltMin: 1,7; OpVoltMax: 5,5; MaxClockFreq: 1 MHz; AddressPins: 3; PageSize_B: 128; WPScheme: Full Array; MemoryOrg: x8; Endurance: 1,000,000; Populated: YES
Y9 = MIC8282: as Y6 on sheet 07 - USB HSIC to Gb Ethernet
Y10 = OSC1159: Crystal; Manufacturer 1: ECS Inc.; Description_: CRYSTAL 25MHz 20pF SMD L3.2W2.5H0.8; Dev Tools Status: Design; Owner: Ciprian Abramov; Tolerance: 10ppm; Load Capacitance: 20pF; Populated: DNP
